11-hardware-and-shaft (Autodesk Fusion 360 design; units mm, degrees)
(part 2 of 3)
sketch "B Facet 180 Triangle 3" plane through (0, -75, 0) normal (0, -1, 0) x axis (-1, 0, 0)
  line L1 (60.9665, 27.066) -> (-2.067, -27.066)
  line L2 (124, -27.066) -> (60.9665, 27.066)
  line L3 (-2.067, -27.066) -> (124, -27.066)
  line L4 (60.9665, 21.7934) -> (8.7304, -23.066)
  line L5 (113.2026, -23.066) -> (60.9665, 21.7934)
  line L6 (8.7304, -23.066) -> (113.2026, -23.066)
  point P1 (0, 0)
  point P2 (-2.067, -27.066)
  point P3 (60.9665, 27.066)
  point P4 (124, -27.066)
  dimension "d477" distance P1 P2 = 2.067 (= "Linear Dimension-2")
  dimension "d478" distance P1 P2 = 27.066 (= "Linear Dimension-3")
  dimension "d479" distance P1 P3 = 60.9665 (= "Linear Dimension-4")
  dimension "d480" distance P1 P3 = 27.066 (= "Linear Dimension-5")
  dimension "d481" distance P1 P4 = 124 (= "Linear Dimension-6")
  dimension "d482" distance P1 P4 = 27.066 (= "Linear Dimension-7")
  dimension "d483" = 4 (= "memberWidth / 2")
extrude "Extrude14" cut sketch "B Facet 180 Triangle 3" profile of L5 L6 L4 against normal blind 4.7 (magnitude of "-( wall + 0.2 mm )")
sketch "B Facet 180 Triangle 4" plane through (0, -75, 0) normal (0, -1, 0) x axis (-1, 0, 0)
  line L1 (124, -27.066) -> (60.9665, 27.066)
  line L2 (124, 27.066) -> (124, -27.066)
  line L3 (60.9665, 27.066) -> (124, 27.066)
  line L4 (120, -18.3583) -> (71.7639, 23.066)
  line L5 (120, 23.066) -> (120, -18.3583)
  line L6 (71.7639, 23.066) -> (120, 23.066)
  point P1 (0, 0)
  point P2 (60.9665, 27.066)
  point P3 (124, -27.066)
  point P4 (124, 27.066)
  dimension "d486" distance P1 P2 = 60.9665 (= "Linear Dimension-2")
  dimension "d487" distance P1 P2 = 27.066 (= "Linear Dimension-3")
  dimension "d488" distance P1 P3 = 124 (= "Linear Dimension-4")
  dimension "d489" distance P1 P3 = 27.066 (= "Linear Dimension-5")
  dimension "d490" distance P1 P4 = 124 (= "Linear Dimension-6")
  dimension "d491" distance P1 P4 = 27.066 (= "Linear Dimension-7")
  dimension "d492" = -4 (= "-memberWidth / 2")
extrude "Extrude15" cut sketch "B Facet 180 Triangle 4" profile of L5 L6 L4 against normal blind 4.7 (magnitude of "-( wall + 0.2 mm )")
fillet "Fillet5" radius 1.5 (= "apertureRadius")
work_plane "WorkPlane11" RotateAngle 135 ExtraOffset 0
work_plane "WorkPlane12" AlongDistance 75 (= "bodyWidth / 2") ExtraOffset 0
sketch "B Facet 225 Triangle 1" plane through (0, -53.033, -53.033) normal (0, -0.7071, -0.7071) x axis (1, 0, 0)
  line L1 (23.9949, -27.066) -> (62.2721, 27.066)
  line L2 (0.1814, 27.066) -> (23.9949, -27.066)
  line L3 (62.2721, 27.066) -> (0.1814, 27.066)
  line L4 (24.81, -18.9852) -> (54.5447, 23.066)
  line L5 (6.311, 23.066) -> (24.81, -18.9852)
  line L6 (54.5447, 23.066) -> (6.311, 23.066)
  point P1 (0, 0)
  point P2 (62.2721, 27.066)
  point P3 (23.9949, -27.066)
  point P4 (0.1814, 27.066)
  dimension "d501" distance P1 P2 = 62.2721 (= "Linear Dimension-2")
  dimension "d502" distance P1 P2 = 27.066 (= "Linear Dimension-3")
  dimension "d503" distance P1 P3 = 23.9949 (= "Linear Dimension-4")
  dimension "d504" distance P1 P3 = 27.066 (= "Linear Dimension-5")
  dimension "d505" distance P1 P4 = 0.1814 (= "Linear Dimension-6")
  dimension "d506" distance P1 P4 = 27.066 (= "Linear Dimension-7")
  dimension "d507" = 4 (= "memberWidth / 2")
extrude "Extrude16" cut sketch "B Facet 225 Triangle 1" profile of L5 L6 L4 against normal blind 4.7 (magnitude of "-( wall + 0.2 mm )")
sketch "B Facet 225 Triangle 2" plane through (0, -53.033, -53.033) normal (0, -0.7071, -0.7071) x axis (1, 0, 0)
  line L1 (0.1814, 27.066) -> (23.9949, -27.066)
  line L2 (-74.6684, -27.066) -> (0.1814, 27.066)
  line L3 (23.9949, -27.066) -> (-74.6684, -27.066)
  line L4 (-1.4863, 20.9235) -> (17.8653, -23.066)
  line L5 (-62.3117, -23.066) -> (-1.4863, 20.9235)
  line L6 (17.8653, -23.066) -> (-62.3117, -23.066)
  point P1 (0, 0)
  point P2 (23.9949, -27.066)
  point P3 (0.1814, 27.066)
  point P4 (-74.6684, -27.066)
  dimension "d510" distance P1 P2 = 23.9949 (= "Linear Dimension-2")
  dimension "d511" distance P1 P2 = 27.066 (= "Linear Dimension-3")
  dimension "d512" distance P1 P3 = 0.1814 (= "Linear Dimension-4")
  dimension "d513" distance P1 P3 = 27.066 (= "Linear Dimension-5")
  dimension "d514" distance P1 P4 = 74.6684 (= "Linear Dimension-6")
  dimension "d515" distance P1 P4 = 27.066 (= "Linear Dimension-7")
  dimension "d516" = -4 (= "-memberWidth / 2")
extrude "Extrude17" cut sketch "B Facet 225 Triangle 2" profile of L5 L6 L4 against normal blind 4.7 (magnitude of "-( wall + 0.2 mm )")
sketch "B Facet 225 Triangle 3" plane through (0, -53.033, -53.033) normal (0, -0.7071, -0.7071) x axis (1, 0, 0)
  line L1 (-74.6684, -27.066) -> (0.1814, 27.066)
  line L2 (-124, 27.066) -> (-74.6684, -27.066)
  line L3 (0.1814, 27.066) -> (-124, 27.066)
  line L4 (-74.1179, -21.7315) -> (-12.1753, 23.066)
  line L5 (-114.9429, 23.066) -> (-74.1179, -21.7315)
  line L6 (-12.1753, 23.066) -> (-114.9429, 23.066)
  point P1 (0, 0)
  point P2 (0.1814, 27.066)
  point P3 (-74.6684, -27.066)
  point P4 (-124, 27.066)
  dimension "d519" distance P1 P2 = 0.1814 (= "Linear Dimension-2")
  dimension "d520" distance P1 P2 = 27.066 (= "Linear Dimension-3")
  dimension "d521" distance P1 P3 = 74.6684 (= "Linear Dimension-4")
  dimension "d522" distance P1 P3 = 27.066 (= "Linear Dimension-5")
  dimension "d523" distance P1 P4 = 124 (= "Linear Dimension-6")
  dimension "d524" distance P1 P4 = 27.066 (= "Linear Dimension-7")
  dimension "d525" = 4 (= "memberWidth / 2")
extrude "Extrude18" cut sketch "B Facet 225 Triangle 3" profile of L5 L6 L4 against normal blind 4.7 (magnitude of "-( wall + 0.2 mm )")
sketch "B Facet 225 Triangle 4" plane through (0, -53.033, -53.033) normal (0, -0.7071, -0.7071) x axis (1, 0, 0)
  line L1 (-124, 27.066) -> (-74.6684, -27.066)
  line L2 (-124, -27.066) -> (-124, 27.066)
  line L3 (-74.6684, -27.066) -> (-124, -27.066)
  line L4 (-120, 16.7383) -> (-83.7255, -23.066)
  line L5 (-120, -23.066) -> (-120, 16.7383)
  line L6 (-83.7255, -23.066) -> (-120, -23.066)
  point P1 (0, 0)
  point P2 (-74.6684, -27.066)
  point P3 (-124, 27.066)
  point P4 (-124, -27.066)
  dimension "d528" distance P1 P2 = 74.6684 (= "Linear Dimension-2")
  dimension "d529" distance P1 P2 = 27.066 (= "Linear Dimension-3")
  dimension "d530" distance P1 P3 = 124 (= "Linear Dimension-4")
  dimension "d531" distance P1 P3 = 27.066 (= "Linear Dimension-5")
  dimension "d532" distance P1 P4 = 124 (= "Linear Dimension-6")
  dimension "d533" distance P1 P4 = 27.066 (= "Linear Dimension-7")
  dimension "d534" = -4 (= "-memberWidth / 2")
extrude "Extrude19" cut sketch "B Facet 225 Triangle 4" profile of L5 L6 L4 against normal blind 4.7 (magnitude of "-( wall + 0.2 mm )")
fillet "Fillet6" radius 1.5 (= "apertureRadius")
work_plane "WorkPlane13" RotateAngle 180 ExtraOffset 0
work_plane "WorkPlane14" AlongDistance 75 (= "bodyWidth / 2") ExtraOffset 0
sketch "B Facet 270 Triangle 1" plane through (0, 0, -75) normal (0, 0, -1) x axis (-1, 0, 0)
  line L1 (36.9655, 27.066) -> (-17.1665, -27.066)
  line L2 (53.4167, -27.066) -> (36.9655, 27.066)
  line L3 (-17.1665, -27.066) -> (53.4167, -27.066)
  line L4 (35.0777, 19.5214) -> (-7.5097, -23.066)
  line L5 (48.0205, -23.066) -> (35.0777, 19.5214)
  line L6 (-7.5097, -23.066) -> (48.0205, -23.066)
  point P1 (0, 0)
  point P2 (-17.1665, -27.066)
  point P3 (36.9655, 27.066)
  point P4 (53.4167, -27.066)
  dimension "d543" distance P1 P2 = 17.1665 (= "Linear Dimension-2")
  dimension "d544" distance P1 P2 = 27.066 (= "Linear Dimension-3")
  dimension "d545" distance P1 P3 = 36.9655 (= "Linear Dimension-4")
  dimension "d546" distance P1 P3 = 27.066 (= "Linear Dimension-5")
  dimension "d547" distance P1 P4 = 53.4167 (= "Linear Dimension-6")
  dimension "d548" distance P1 P4 = 27.066 (= "Linear Dimension-7")
  dimension "d549" = 4 (= "memberWidth / 2")
extrude "Extrude20" cut sketch "B Facet 270 Triangle 1" profile of L5 L6 L4 against normal blind 4.7 (magnitude of "-( wall + 0.2 mm )")
sketch "B Facet 270 Triangle 2" plane through (0, 0, -75) normal (0, 0, -1) x axis (-1, 0, 0)
  line L1 (53.4167, -27.066) -> (36.9655, 27.066)
  line L2 (124, 27.066) -> (53.4167, -27.066)
  line L3 (36.9655, 27.066) -> (124, 27.066)
  line L4 (55.5648, -20.3777) -> (42.3618, 23.066)
  line L5 (112.2115, 23.066) -> (55.5648, -20.3777)
  line L6 (42.3618, 23.066) -> (112.2115, 23.066)
  point P1 (0, 0)
  point P2 (36.9655, 27.066)
  point P3 (53.4167, -27.066)
  point P4 (124, 27.066)
  dimension "d552" distance P1 P2 = 36.9655 (= "Linear Dimension-2")
  dimension "d553" distance P1 P2 = 27.066 (= "Linear Dimension-3")
  dimension "d554" distance P1 P3 = 53.4167 (= "Linear Dimension-4")
  dimension "d555" distance P1 P3 = 27.066 (= "Linear Dimension-5")
  dimension "d556" distance P1 P4 = 124 (= "Linear Dimension-6")
  dimension "d557" distance P1 P4 = 27.066 (= "Linear Dimension-7")
  dimension "d558" = -4 (= "-memberWidth / 2")
extrude "Extrude21" cut sketch "B Facet 270 Triangle 2" profile of L5 L6 L4 against normal blind 4.7 (magnitude of "-( wall + 0.2 mm )")
sketch "B Facet 270 Triangle 3" plane through (0, 0, -75) normal (0, 0, -1) x axis (-1, 0, 0)
  line L1 (124, 27.066) -> (53.4167, -27.066)
  line L2 (124, -27.066) -> (124, 27.066)
  line L3 (53.4167, -27.066) -> (124, -27.066)
  line L4 (120, 18.9574) -> (65.2053, -23.066)
  line L5 (120, -23.066) -> (120, 18.9574)
  line L6 (65.2053, -23.066) -> (120, -23.066)
  point P1 (0, 0)
  point P2 (53.4167, -27.066)
  point P3 (124, 27.066)
  point P4 (124, -27.066)
  dimension "d561" distance P1 P2 = 53.4167 (= "Linear Dimension-2")
  dimension "d562" distance P1 P2 = 27.066 (= "Linear Dimension-3")
  dimension "d563" distance P1 P3 = 124 (= "Linear Dimension-4")
  dimension "d564" distance P1 P3 = 27.066 (= "Linear Dimension-5")
  dimension "d565" distance P1 P4 = 124 (= "Linear Dimension-6")
  dimension "d566" distance P1 P4 = 27.066 (= "Linear Dimension-7")
  dimension "d567" = 4 (= "memberWidth / 2")
extrude "Extrude22" cut sketch "B Facet 270 Triangle 3" profile of L5 L6 L4 against normal blind 4.7 (magnitude of "-( wall + 0.2 mm )")
fillet "Fillet7" radius 1.5 (= "apertureRadius")
work_plane "WorkPlane15" RotateAngle 225 ExtraOffset 0
work_plane "WorkPlane16" AlongDistance 75 (= "bodyWidth / 2") ExtraOffset 0
sketch "B Facet 315 Triangle 1" plane through (0, 53.033, -53.033) normal (0, 0.7071, -0.7071) x axis (1, 0, 0)
  line L1 (-82.0711, -27.066) -> (-43.7939, 27.066)
  line L2 (-124, 27.066) -> (-82.0711, -27.066)
  line L3 (-43.7939, 27.066) -> (-124, 27.066)
  line L4 (-82.2175, -20.3449) -> (-51.5213, 23.066)
  line L5 (-115.8422, 23.066) -> (-82.2175, -20.3449)
  line L6 (-51.5213, 23.066) -> (-115.8422, 23.066)
  point P1 (0, 0)
  point P2 (-43.7939, 27.066)
  point P3 (-82.0711, -27.066)
  point P4 (-124, 27.066)
  dimension "d576" distance P1 P2 = 43.7939 (= "Linear Dimension-2")
  dimension "d577" distance P1 P2 = 27.066 (= "Linear Dimension-3")
  dimension "d578" distance P1 P3 = 82.0711 (= "Linear Dimension-4")
  dimension "d579" distance P1 P3 = 27.066 (= "Linear Dimension-5")
  dimension "d580" distance P1 P4 = 124 (= "Linear Dimension-6")
  dimension "d581" distance P1 P4 = 27.066 (= "Linear Dimension-7")
  dimension "d582" = 4 (= "memberWidth / 2")
extrude "Extrude23" cut sketch "B Facet 315 Triangle 1" profile of L5 L6 L4 against normal blind 4.7 (magnitude of "-( wall + 0.2 mm )")
sketch "B Facet 315 Triangle 2" plane through (0, 53.033, -53.033) normal (0, 0.7071, -0.7071) x axis (1, 0, 0)
  line L1 (-124, 27.066) -> (-82.0711, -27.066)
  line L2 (-124, -27.066) -> (-124, 27.066)
  line L3 (-82.0711, -27.066) -> (-124, -27.066)
  line L4 (-120, 15.3697) -> (-90.2289, -23.066)
  line L5 (-120, -23.066) -> (-120, 15.3697)
  line L6 (-90.2289, -23.066) -> (-120, -23.066)
  point P1 (0, 0)
  point P2 (-82.0711, -27.066)
  point P3 (-124, 27.066)
  point P4 (-124, -27.066)
  dimension "d585" distance P1 P2 = 82.0711 (= "Linear Dimension-2")
  dimension "d586" distance P1 P2 = 27.066 (= "Linear Dimension-3")
  dimension "d587" distance P1 P3 = 124 (= "Linear Dimension-4")
  dimension "d588" distance P1 P3 = 27.066 (= "Linear Dimension-5")
  dimension "d589" distance P1 P4 = 124 (= "Linear Dimension-6")
  dimension "d590" distance P1 P4 = 27.066 (= "Linear Dimension-7")
  dimension "d591" = -4 (= "-memberWidth / 2")
extrude "Extrude24" cut sketch "B Facet 315 Triangle 2" profile of L5 L6 L4 against normal blind 4.7 (magnitude of "-( wall + 0.2 mm )")
fillet "Fillet8" radius 1.5 (= "apertureRadius")
work_plane "WorkPlane17" AlongDistance 0.5 (= "qFront") ExtraOffset 0
sketch "A Central Carrier sketch" plane through (0.3536, 0.3536, 0) normal (0.7071, 0.7071, 0) x axis (0, 0, 1)
  circle C1 centre (0, 0) radius 26
  dimension "d598" diameter C1 = 52 (= "carrierOD")
extrude "Extrude25" new body sketch "A Central Carrier sketch" along normal blind 18 (= "spokeDepth")
work_plane "WorkPlane18" AlongDistance 0.5 (= "qFront") ExtraOffset 0
sketch "A Spoke 1 Profile" plane through (0.3536, 0.3536, 0) normal (0.7071, 0.7071, 0) x axis (0, 0, 1)
  line L1 (37.3643, -145.3579) -> (-4.7984, -1.4054)
  line L2 (46.9611, -142.547) -> (37.3643, -145.3579)
  line L3 (4.7984, 1.4054) -> (46.9611, -142.547)
  line L4 (-4.7984, -1.4054) -> (4.7984, 1.4054)
  point P1 (0, 0)
  point P2 (-4.7984, -1.4054)
  point P3 (37.3643, -145.3579)
  point P4 (46.9611, -142.547)
  point P5 (4.7984, 1.4054)
  dimension "d603" distance P1 P2 = 4.7984 (= "Linear Dimension-2")
  dimension "d604" distance P1 P2 = 1.4054 (= "Linear Dimension-3")
  dimension "d605" distance P1 P3 = 37.3643 (= "Linear Dimension-4")
  dimension "d606" distance P1 P3 = 145.3579 (= "Linear Dimension-5")
  dimension "d607" distance P1 P4 = 46.9611 (= "Linear Dimension-6")
  dimension "d608" distance P1 P4 = 142.547 (= "Linear Dimension-7")
  dimension "d609" distance P1 P5 = 4.7984 (= "Linear Dimension-8")
  dimension "d610" distance P1 P5 = 1.4054 (= "Linear Dimension-9")
extrude "Extrude26" add sketch "A Spoke 1 Profile" along normal blind 18 (= "spokeDepth")
sketch "A Spoke 2 Profile" plane through (0.3536, 0.3536, 0) normal (0.7071, 0.7071, 0) x axis (0, 0, 1)
  line L1 (126.9012, -80.1317) -> (-2.5272, -4.3143)
  line L2 (131.9557, -71.5031) -> (126.9012, -80.1317)
  line L3 (2.5272, 4.3143) -> (131.9557, -71.5031)
  line L4 (-2.5272, -4.3143) -> (2.5272, 4.3143)
  point P1 (0, 0)
  point P2 (-2.5272, -4.3143)
  point P3 (126.9012, -80.1317)
  point P4 (131.9557, -71.5031)
  point P5 (2.5272, 4.3143)
  dimension "d613" distance P1 P2 = 2.5272 (= "Linear Dimension-2")
  dimension "d614" distance P1 P2 = 4.3143 (= "Linear Dimension-3")
  dimension "d615" distance P1 P3 = 126.9012 (= "Linear Dimension-4")
  dimension "d616" distance P1 P3 = 80.1317 (= "Linear Dimension-5")
  dimension "d617" distance P1 P4 = 131.9557 (= "Linear Dimension-6")
  dimension "d618" distance P1 P4 = 71.5031 (= "Linear Dimension-7")
  dimension "d619" distance P1 P5 = 2.5272 (= "Linear Dimension-8")
  dimension "d620" distance P1 P5 = 4.3143 (= "Linear Dimension-9")
extrude "Extrude27" add sketch "A Spoke 2 Profile" along normal blind 18 (= "spokeDepth")
sketch "A Spoke 3 Profile" plane through (0.3536, 0.3536, 0) normal (0.7071, 0.7071, 0) x axis (0, 0, 1)
  line L1 (131.9557, 71.5031) -> (2.5272, -4.3143)
  line L2 (126.9012, 80.1317) -> (131.9557, 71.5031)
  line L3 (-2.5272, 4.3143) -> (126.9012, 80.1317)
  line L4 (2.5272, -4.3143) -> (-2.5272, 4.3143)
  point P1 (0, 0)
  point P2 (2.5272, -4.3143)
  point P3 (131.9557, 71.5031)
  point P4 (126.9012, 80.1317)
  point P5 (-2.5272, 4.3143)
  dimension "d623" distance P1 P2 = 2.5272 (= "Linear Dimension-2")
  dimension "d624" distance P1 P2 = 4.3143 (= "Linear Dimension-3")
  dimension "d625" distance P1 P3 = 131.9557 (= "Linear Dimension-4")
  dimension "d626" distance P1 P3 = 71.5031 (= "Linear Dimension-5")
  dimension "d627" distance P1 P4 = 126.9012 (= "Linear Dimension-6")
  dimension "d628" distance P1 P4 = 80.1317 (= "Linear Dimension-7")
  dimension "d629" distance P1 P5 = 2.5272 (= "Linear Dimension-8")
  dimension "d630" distance P1 P5 = 4.3143 (= "Linear Dimension-9")
extrude "Extrude28" add sketch "A Spoke 3 Profile" along normal blind 18 (= "spokeDepth")
sketch "A Spoke 4 Profile" plane through (0.3536, 0.3536, 0) normal (0.7071, 0.7071, 0) x axis (0, 0, 1)
  line L1 (46.9611, 142.547) -> (4.7984, -1.4054)
  line L2 (37.3643, 145.3579) -> (46.9611, 142.547)
  line L3 (-4.7984, 1.4054) -> (37.3643, 145.3579)
  line L4 (4.7984, -1.4054) -> (-4.7984, 1.4054)
  point P1 (0, 0)
  point P2 (4.7984, -1.4054)
  point P3 (46.9611, 142.547)
  point P4 (37.3643, 145.3579)
  point P5 (-4.7984, 1.4054)
  dimension "d633" distance P1 P2 = 4.7984 (= "Linear Dimension-2")
  dimension "d634" distance P1 P2 = 1.4054 (= "Linear Dimension-3")
  dimension "d635" distance P1 P3 = 46.9611 (= "Linear Dimension-4")
  dimension "d636" distance P1 P3 = 142.547 (= "Linear Dimension-5")
  dimension "d637" distance P1 P4 = 37.3643 (= "Linear Dimension-6")
  dimension "d638" distance P1 P4 = 145.3579 (= "Linear Dimension-7")
  dimension "d639" distance P1 P5 = 4.7984 (= "Linear Dimension-8")
  dimension "d640" distance P1 P5 = 1.4054 (= "Linear Dimension-9")
extrude "Extrude29" add sketch "A Spoke 4 Profile" along normal blind 18 (= "spokeDepth")
sketch "A Spoke 5 Profile" plane through (0.3536, 0.3536, 0) normal (0.7071, 0.7071, 0) x axis (0, 0, 1)
  line L1 (-37.3643, 145.3579) -> (4.7984, 1.4054)
  line L2 (-46.9611, 142.547) -> (-37.3643, 145.3579)
  line L3 (-4.7984, -1.4054) -> (-46.9611, 142.547)
  line L4 (4.7984, 1.4054) -> (-4.7984, -1.4054)
  point P1 (0, 0)
  point P2 (4.7984, 1.4054)
  point P3 (-37.3643, 145.3579)
  point P4 (-46.9611, 142.547)
  point P5 (-4.7984, -1.4054)
  dimension "d643" distance P1 P2 = 4.7984 (= "Linear Dimension-2")
  dimension "d644" distance P1 P2 = 1.4054 (= "Linear Dimension-3")
  dimension "d645" distance P1 P3 = 37.3643 (= "Linear Dimension-4")
  dimension "d646" distance P1 P3 = 145.3579 (= "Linear Dimension-5")
  dimension "d647" distance P1 P4 = 46.9611 (= "Linear Dimension-6")
  dimension "d648" distance P1 P4 = 142.547 (= "Linear Dimension-7")
  dimension "d649" distance P1 P5 = 4.7984 (= "Linear Dimension-8")
  dimension "d650" distance P1 P5 = 1.4054 (= "Linear Dimension-9")
extrude "Extrude30" add sketch "A Spoke 5 Profile" along normal blind 18 (= "spokeDepth")
sketch "A Spoke 6 Profile" plane through (0.3536, 0.3536, 0) normal (0.7071, 0.7071, 0) x axis (0, 0, 1)
  line L1 (-126.9012, 80.1317) -> (2.5272, 4.3143)
  line L2 (-131.9557, 71.5031) -> (-126.9012, 80.1317)
  line L3 (-2.5272, -4.3143) -> (-131.9557, 71.5031)
  line L4 (2.5272, 4.3143) -> (-2.5272, -4.3143)
  point P1 (0, 0)
  point P2 (2.5272, 4.3143)
  point P3 (-126.9012, 80.1317)
  point P4 (-131.9557, 71.5031)
  point P5 (-2.5272, -4.3143)
  dimension "d653" distance P1 P2 = 2.5272 (= "Linear Dimension-2")
  dimension "d654" distance P1 P2 = 4.3143 (= "Linear Dimension-3")
  dimension "d655" distance P1 P3 = 126.9012 (= "Linear Dimension-4")
  dimension "d656" distance P1 P3 = 80.1317 (= "Linear Dimension-5")
  dimension "d657" distance P1 P4 = 131.9557 (= "Linear Dimension-6")
  dimension "d658" distance P1 P4 = 71.5031 (= "Linear Dimension-7")
  dimension "d659" distance P1 P5 = 2.5272 (= "Linear Dimension-8")
  dimension "d660" distance P1 P5 = 4.3143 (= "Linear Dimension-9")
extrude "Extrude31" add sketch "A Spoke 6 Profile" along normal blind 18 (= "spokeDepth")
sketch "A Spoke 7 Profile" plane through (0.3536, 0.3536, 0) normal (0.7071, 0.7071, 0) x axis (0, 0, 1)
  line L1 (-131.9557, -71.5031) -> (-2.5272, 4.3143)
  line L2 (-126.9012, -80.1317) -> (-131.9557, -71.5031)
  line L3 (2.5272, -4.3143) -> (-126.9012, -80.1317)
  line L4 (-2.5272, 4.3143) -> (2.5272, -4.3143)
  point P1 (0, 0)
  point P2 (-2.5272, 4.3143)
  point P3 (-131.9557, -71.5031)
  point P4 (-126.9012, -80.1317)
  point P5 (2.5272, -4.3143)
  dimension "d663" distance P1 P2 = 2.5272 (= "Linear Dimension-2")
  dimension "d664" distance P1 P2 = 4.3143 (= "Linear Dimension-3")
  dimension "d665" distance P1 P3 = 131.9557 (= "Linear Dimension-4")
  dimension "d666" distance P1 P3 = 71.5031 (= "Linear Dimension-5")
  dimension "d667" distance P1 P4 = 126.9012 (= "Linear Dimension-6")
  dimension "d668" distance P1 P4 = 80.1317 (= "Linear Dimension-7")
  dimension "d669" distance P1 P5 = 2.5272 (= "Linear Dimension-8")
  dimension "d670" distance P1 P5 = 4.3143 (= "Linear Dimension-9")
extrude "Extrude32" add sketch "A Spoke 7 Profile" along normal blind 18 (= "spokeDepth")
sketch "A Spoke 8 Profile" plane through (0.3536, 0.3536, 0) normal (0.7071, 0.7071, 0) x axis (0, 0, 1)
  line L1 (-46.9611, -142.547) -> (-4.7984, 1.4054)
  line L2 (-37.3643, -145.3579) -> (-46.9611, -142.547)
  line L3 (4.7984, 1.4054) -> (-37.3643, -145.3579)
  line L4 (-4.7984, 1.4054) -> (4.7984, 1.4054)
  point P1 (0, 0)
  point P2 (-4.7984, 1.4054)
  point P3 (-46.9611, -142.547)
  point P4 (-37.3643, -145.3579)
  point P5 (4.7984, 1.4054)
  dimension "d673" distance P1 P2 = 4.7984 (= "Linear Dimension-2")
  dimension "d674" distance P1 P2 = 1.4054 (= "Linear Dimension-3")
  dimension "d675" distance P1 P3 = 46.9611 (= "Linear Dimension-4")
  dimension "d676" distance P1 P3 = 142.547 (= "Linear Dimension-5")
  dimension "d677" distance P1 P4 = 37.3643 (= "Linear Dimension-6")
  dimension "d678" distance P1 P4 = 145.3579 (= "Linear Dimension-7")
  dimension "d679" distance P1 P5 = 4.7984 (= "Linear Dimension-8")
  dimension "d680" distance P1 P5 = 1.4054 (= "Linear Dimension-9")
extrude "Extrude33" add sketch "A Spoke 8 Profile" along normal blind 18 (= "spokeDepth")
sketch "Spoke Outer Envelope" plane through (0, 0, 0) normal (1, 0, 0) x axis (0, 0, -1)
  line L1 (31.066, 75) -> (75, 31.066)
  line L2 (-31.066, 75) -> (31.066, 75)
  line L3 (-75, 31.066) -> (-31.066, 75)
  line L4 (-75, -31.066) -> (-75, 31.066)
  line L5 (-31.066, -75) -> (-75, -31.066)
  line L6 (31.066, -75) -> (-31.066, -75)
  line L7 (75, -31.066) -> (31.066, -75)
  line L8 (75, 31.066) -> (75, -31.066)
  point P1 (0, 0)
  point P10 (0, 0)
  point P3 (31.066, 75)
  point P8 (31.066, -75)
  coincident P1 P10
  horizontal L2
  dimension "d683" distance P3 P8 = 150 (= "bodyWidth")
extrude "Extrude34" sketch "Spoke Outer Envelope" distance 260 (= "bodyLength")
fillet "Fillet9" radius 1 (= "rootRadius")
work_plane "WorkPlane19" AlongDistance 10.6 (= "qFrontBack") ExtraOffset 0
sketch "A Rear Carrier Clearance sketch" plane through (7.4953, 7.4953, 0) normal (0.7071, 0.7071, 0) x axis (0, 0, 1)
  circle C1 centre (0, 0) radius 23
  dimension "d690" diameter C1 = 46 (= "rearCarrierClearance")
extrude "Extrude35" cut sketch "A Rear Carrier Clearance sketch" along normal blind 18 (= "spokeDepth")
work_plane "WorkPlane20" AlongDistance 0.5 (= "qFront") ExtraOffset 0
sketch "A Seal Relief sketch" plane through (0.3536, 0.3536, 0) normal (0.7071, 0.7071, 0) x axis (0, 0, 1)
  circle C1 centre (0, 0) radius 9.75
  dimension "d695" diameter C1 = 19.5 (= "raceRelief")
extrude "Extrude36" cut sketch "A Seal Relief sketch" along normal blind 10.1 (= "frontSeatDepth + shoulder")
work_plane "WorkPlane21" AlongDistance 0.5 (= "qFront") ExtraOffset 0
sketch "A Front Bearing Seat sketch" plane through (0.3536, 0.3536, 0) normal (0.7071, 0.7071, 0) x axis (0, 0, 1)
  circle C1 centre (0, 0) radius 11.1
  dimension "d700" diameter C1 = 22.2 (= "seatDiameter")
extrude "Extrude37" cut sketch "A Front Bearing Seat sketch" along normal blind 7.1 (= "frontSeatDepth")
work_plane "WorkPlane22" AlongDistance 0.5 (= "qFront") ExtraOffset 0
sketch "A Support Bolt seed" plane through (0.3536, 0.3536, 0) normal (0.7071, 0.7071, 0) x axis (0, 0, 1)
  line L1 (17, 0) -> (0, 0)
  circle C1 centre (17, 0) radius 1.65
  point P1 (0, 0)
  point P2 (17, 0)
  horizontal L1
  dimension "d705" distance P1 P2 = 17 (= "supportCircle / 2")
  dimension "d706" diameter C1 = 3.3 (= "m3Clearance")
extrude "Extrude38" cut sketch "A Support Bolt seed" profile of C1 along normal blind 10.1 (= "frontSeatDepth + shoulder")
circular_pattern "C-Pattern1" TotalAngle 360
work_plane "WorkPlane23" AlongDistance 0.5 (= "qFront") ExtraOffset 0
sketch "A Front Bearing Boss sketch" plane through (0.3536, 0.3536, 0) normal (0.7071, 0.7071, 0) x axis (0, 0, 1)
  circle C1 centre (0, 0) radius 22
  dimension "d713" diameter C1 = 44 (= "coreOD")
chamfer "Chamfer1" distance 0.4 (= "entryChamfer")
work_plane "WorkPlane24" AlongDistance 75 (= "bodyWidth / 2") ExtraOffset 0
sketch "A Collar Driver Corridors" plane through (0, 0, 75) normal (0, 0, 1) x axis (1, 0, 0)
  circle C1 centre (6.7175, 15.9099) radius 3
  circle C2 centre (15.9099, 6.7175) radius 3
  point P1 (0, 0)
  point P2 (6.7175, 15.9099)
  point P3 (15.9099, 6.7175)
  dimension "d717" distance P1 P2 = 6.7175 (= "abs(( 16 mm + ( -6.5 mm ) ) / sqrt(2))")
  dimension "d718" distance P1 P2 = 15.9099 (= "abs(( 16 mm - ( -6.5 mm ) ) / sqrt(2))")
  dimension "d719" diameter C1 = 6
  dimension "d720" distance P1 P3 = 15.9099 (= "abs(( 16 mm + ( 6.5 mm ) ) / sqrt(2))")
  dimension "d721" distance P1 P3 = 6.7175 (= "abs(( 16 mm - ( 6.5 mm ) ) / sqrt(2))")
  dimension "d722" diameter C2 = 6
extrude "Extrude39" cut sketch "A Collar Driver Corridors" against normal blind 75 (magnitude of "-( bodyWidth / 2 )")
work_plane "WorkPlane17" ExtraOffset 0
sketch "B Central Carrier sketch" plane through (-0.3536, -0.3536, 0) normal (0.7071, 0.7071, 0) x axis (0, 0, 1)
  circle C1 centre (0, 0) radius 38
  dimension "d727" diameter C1 = 76 (= "mountOD")
extrude "Extrude25" new body sketch "B Central Carrier sketch" no distance stored
work_plane "WorkPlane18" ExtraOffset 0
sketch "B Spoke 1 Profile" plane through (-0.3536, -0.3536, 0) normal (0.7071, 0.7071, 0) x axis (0, 0, 1)
  line L1 (37.3643, -145.3579) -> (-4.7984, -1.4054)
  line L2 (46.9611, -142.547) -> (37.3643, -145.3579)
  line L3 (4.7984, 1.4054) -> (46.9611, -142.547)
  line L4 (-4.7984, -1.4054) -> (4.7984, 1.4054)
  point P1 (0, 0)
  point P2 (-4.7984, -1.4054)
  point P3 (37.3643, -145.3579)
  point P4 (46.9611, -142.547)
  point P5 (4.7984, 1.4054)
  dimension "d732" distance P1 P2 = 4.7984 (= "Linear Dimension-2")
  dimension "d733" distance P1 P2 = 1.4054 (= "Linear Dimension-3")
  dimension "d734" distance P1 P3 = 37.3643 (= "Linear Dimension-4")
  dimension "d735" distance P1 P3 = 145.3579 (= "Linear Dimension-5")
  dimension "d736" distance P1 P4 = 46.9611 (= "Linear Dimension-6")
  dimension "d737" distance P1 P4 = 142.547 (= "Linear Dimension-7")
  dimension "d738" distance P1 P5 = 4.7984 (= "Linear Dimension-8")
  dimension "d739" distance P1 P5 = 1.4054 (= "Linear Dimension-9")
extrude "Extrude26" add sketch "B Spoke 1 Profile" no distance stored
sketch "B Spoke 2 Profile" plane through (-0.3536, -0.3536, 0) normal (0.7071, 0.7071, 0) x axis (0, 0, 1)
  line L1 (126.9012, -80.1317) -> (-2.5272, -4.3143)
  line L2 (131.9557, -71.5031) -> (126.9012, -80.1317)
  line L3 (2.5272, 4.3143) -> (131.9557, -71.5031)
  line L4 (-2.5272, -4.3143) -> (2.5272, 4.3143)
  point P1 (0, 0)
  point P2 (-2.5272, -4.3143)
  point P3 (126.9012, -80.1317)
  point P4 (131.9557, -71.5031)
  point P5 (2.5272, 4.3143)
  dimension "d742" distance P1 P2 = 2.5272 (= "Linear Dimension-2")
  dimension "d743" distance P1 P2 = 4.3143 (= "Linear Dimension-3")
  dimension "d744" distance P1 P3 = 126.9012 (= "Linear Dimension-4")
  dimension "d745" distance P1 P3 = 80.1317 (= "Linear Dimension-5")
  dimension "d746" distance P1 P4 = 131.9557 (= "Linear Dimension-6")
  dimension "d747" distance P1 P4 = 71.5031 (= "Linear Dimension-7")
  dimension "d748" distance P1 P5 = 2.5272 (= "Linear Dimension-8")
  dimension "d749" distance P1 P5 = 4.3143 (= "Linear Dimension-9")
extrude "Extrude27" add sketch "B Spoke 2 Profile" no distance stored
sketch "B Spoke 3 Profile" plane through (-0.3536, -0.3536, 0) normal (0.7071, 0.7071, 0) x axis (0, 0, 1)
  line L1 (131.9557, 71.5031) -> (2.5272, -4.3143)
  line L2 (126.9012, 80.1317) -> (131.9557, 71.5031)
  line L3 (-2.5272, 4.3143) -> (126.9012, 80.1317)
  line L4 (2.5272, -4.3143) -> (-2.5272, 4.3143)
  point P1 (0, 0)
  point P2 (2.5272, -4.3143)
  point P3 (131.9557, 71.5031)
  point P4 (126.9012, 80.1317)
  point P5 (-2.5272, 4.3143)
  dimension "d752" distance P1 P2 = 2.5272 (= "Linear Dimension-2")
  dimension "d753" distance P1 P2 = 4.3143 (= "Linear Dimension-3")
  dimension "d754" distance P1 P3 = 131.9557 (= "Linear Dimension-4")
  dimension "d755" distance P1 P3 = 71.5031 (= "Linear Dimension-5")
  dimension "d756" distance P1 P4 = 126.9012 (= "Linear Dimension-6")
  dimension "d757" distance P1 P4 = 80.1317 (= "Linear Dimension-7")
  dimension "d758" distance P1 P5 = 2.5272 (= "Linear Dimension-8")
  dimension "d759" distance P1 P5 = 4.3143 (= "Linear Dimension-9")
extrude "Extrude28" add sketch "B Spoke 3 Profile" no distance stored
sketch "B Spoke 4 Profile" plane through (-0.3536, -0.3536, 0) normal (0.7071, 0.7071, 0) x axis (0, 0, 1)
  line L1 (46.9611, 142.547) -> (4.7984, -1.4054)
  line L2 (37.3643, 145.3579) -> (46.9611, 142.547)
  line L3 (-4.7984, 1.4054) -> (37.3643, 145.3579)
  line L4 (4.7984, -1.4054) -> (-4.7984, 1.4054)
  point P1 (0, 0)
  point P2 (4.7984, -1.4054)
  point P3 (46.9611, 142.547)
  point P4 (37.3643, 145.3579)
  point P5 (-4.7984, 1.4054)
  dimension "d762" distance P1 P2 = 4.7984 (= "Linear Dimension-2")
  dimension "d763" distance P1 P2 = 1.4054 (= "Linear Dimension-3")
  dimension "d764" distance P1 P3 = 46.9611 (= "Linear Dimension-4")
  dimension "d765" distance P1 P3 = 142.547 (= "Linear Dimension-5")
  dimension "d766" distance P1 P4 = 37.3643 (= "Linear Dimension-6")
  dimension "d767" distance P1 P4 = 145.3579 (= "Linear Dimension-7")
  dimension "d768" distance P1 P5 = 4.7984 (= "Linear Dimension-8")
  dimension "d769" distance P1 P5 = 1.4054 (= "Linear Dimension-9")
extrude "Extrude29" add sketch "B Spoke 4 Profile" no distance stored
sketch "B Spoke 5 Profile" plane through (-0.3536, -0.3536, 0) normal (0.7071, 0.7071, 0) x axis (0, 0, 1)
  line L1 (-37.3643, 145.3579) -> (4.7984, 1.4054)
  line L2 (-46.9611, 142.547) -> (-37.3643, 145.3579)
  line L3 (-4.7984, -1.4054) -> (-46.9611, 142.547)
  line L4 (4.7984, 1.4054) -> (-4.7984, -1.4054)
  point P1 (0, 0)
  point P2 (4.7984, 1.4054)
  point P3 (-37.3643, 145.3579)
  point P4 (-46.9611, 142.547)
  point P5 (-4.7984, -1.4054)
  dimension "d772" distance P1 P2 = 4.7984 (= "Linear Dimension-2")
  dimension "d773" distance P1 P2 = 1.4054 (= "Linear Dimension-3")
  dimension "d774" distance P1 P3 = 37.3643 (= "Linear Dimension-4")
  dimension "d775" distance P1 P3 = 145.3579 (= "Linear Dimension-5")
  dimension "d776" distance P1 P4 = 46.9611 (= "Linear Dimension-6")
  dimension "d777" distance P1 P4 = 142.547 (= "Linear Dimension-7")
  dimension "d778" distance P1 P5 = 4.7984 (= "Linear Dimension-8")
  dimension "d779" distance P1 P5 = 1.4054 (= "Linear Dimension-9")
extrude "Extrude30" add sketch "B Spoke 5 Profile" no distance stored
sketch "B Spoke 6 Profile" plane through (-0.3536, -0.3536, 0) normal (0.7071, 0.7071, 0) x axis (0, 0, 1)
  line L1 (-126.9012, 80.1317) -> (2.5272, 4.3143)
  line L2 (-131.9557, 71.5031) -> (-126.9012, 80.1317)
  line L3 (-2.5272, -4.3143) -> (-131.9557, 71.5031)
  line L4 (2.5272, 4.3143) -> (-2.5272, -4.3143)
  point P1 (0, 0)
  point P2 (2.5272, 4.3143)
  point P3 (-126.9012, 80.1317)
  point P4 (-131.9557, 71.5031)
  point P5 (-2.5272, -4.3143)
  dimension "d782" distance P1 P2 = 2.5272 (= "Linear Dimension-2")
  dimension "d783" distance P1 P2 = 4.3143 (= "Linear Dimension-3")
  dimension "d784" distance P1 P3 = 126.9012 (= "Linear Dimension-4")
  dimension "d785" distance P1 P3 = 80.1317 (= "Linear Dimension-5")
  dimension "d786" distance P1 P4 = 131.9557 (= "Linear Dimension-6")
  dimension "d787" distance P1 P4 = 71.5031 (= "Linear Dimension-7")
  dimension "d788" distance P1 P5 = 2.5272 (= "Linear Dimension-8")
  dimension "d789" distance P1 P5 = 4.3143 (= "Linear Dimension-9")
extrude "Extrude31" add sketch "B Spoke 6 Profile" no distance stored
sketch "B Spoke 7 Profile" plane through (-0.3536, -0.3536, 0) normal (0.7071, 0.7071, 0) x axis (0, 0, 1)
  line L1 (-131.9557, -71.5031) -> (-2.5272, 4.3143)
  line L2 (-126.9012, -80.1317) -> (-131.9557, -71.5031)
  line L3 (2.5272, -4.3143) -> (-126.9012, -80.1317)
  line L4 (-2.5272, 4.3143) -> (2.5272, -4.3143)
  point P1 (0, 0)
  point P2 (-2.5272, 4.3143)
  point P3 (-131.9557, -71.5031)
  point P4 (-126.9012, -80.1317)
  point P5 (2.5272, -4.3143)
  dimension "d792" distance P1 P2 = 2.5272 (= "Linear Dimension-2")
  dimension "d793" distance P1 P2 = 4.3143 (= "Linear Dimension-3")
  dimension "d794" distance P1 P3 = 131.9557 (= "Linear Dimension-4")
  dimension "d795" distance P1 P3 = 71.5031 (= "Linear Dimension-5")
  dimension "d796" distance P1 P4 = 126.9012 (= "Linear Dimension-6")
  dimension "d797" distance P1 P4 = 80.1317 (= "Linear Dimension-7")
  dimension "d798" distance P1 P5 = 2.5272 (= "Linear Dimension-8")
  dimension "d799" distance P1 P5 = 4.3143 (= "Linear Dimension-9")
extrude "Extrude32" add sketch "B Spoke 7 Profile" no distance stored
sketch "B Spoke 8 Profile" plane through (-0.3536, -0.3536, 0) normal (0.7071, 0.7071, 0) x axis (0, 0, 1)
  line L1 (-46.9611, -142.547) -> (-4.7984, 1.4054)
  line L2 (-37.3643, -145.3579) -> (-46.9611, -142.547)
  line L3 (4.7984, 1.4054) -> (-37.3643, -145.3579)
  line L4 (-4.7984, 1.4054) -> (4.7984, 1.4054)
  point P1 (0, 0)
  point P2 (-4.7984, 1.4054)
  point P3 (-46.9611, -142.547)
  point P4 (-37.3643, -145.3579)
  point P5 (4.7984, 1.4054)
  dimension "d802" distance P1 P2 = 4.7984 (= "Linear Dimension-2")
  dimension "d803" distance P1 P2 = 1.4054 (= "Linear Dimension-3")
  dimension "d804" distance P1 P3 = 46.9611 (= "Linear Dimension-4")
  dimension "d805" distance P1 P3 = 142.547 (= "Linear Dimension-5")
  dimension "d806" distance P1 P4 = 37.3643 (= "Linear Dimension-6")
  dimension "d807" distance P1 P4 = 145.3579 (= "Linear Dimension-7")
  dimension "d808" distance P1 P5 = 4.7984 (= "Linear Dimension-8")
  dimension "d809" distance P1 P5 = 1.4054 (= "Linear Dimension-9")
extrude "Extrude33" add sketch "B Spoke 8 Profile" no distance stored
sketch "Spoke Outer Envelope" plane through (0, 0, 0) normal (1, 0, 0) x axis (0, 0, -1)
  line L1 (31.066, 75) -> (75, 31.066)
  line L2 (-31.066, 75) -> (31.066, 75)
  line L3 (-75, 31.066) -> (-31.066, 75)
  line L4 (-75, -31.066) -> (-75, 31.066)
  line L5 (-31.066, -75) -> (-75, -31.066)
  line L6 (31.066, -75) -> (-31.066, -75)
  line L7 (75, -31.066) -> (31.066, -75)
  line L8 (75, 31.066) -> (75, -31.066)
  point P1 (0, 0)
  point P10 (0, 0)
  point P3 (31.066, 75)
  point P8 (31.066, -75)
  coincident P1 P10
  horizontal L2
  dimension "d812" distance P3 P8 = 150 (= "bodyWidth")
extrude "Extrude34" sketch "Spoke Outer Envelope" distance 260 (= "bodyLength")
fillet "Fillet9" radius 1 (= "rootRadius")
work_plane "WorkPlane19" ExtraOffset 0
sketch "B Open Hub Cavity sketch" plane through (-0.3536, -0.3536, 0) normal (0.7071, 0.7071, 0) x axis (0, 0, 1)
  circle C1 centre (0, 0) radius 25.15
  dimension "d819" diameter C1 = 50.3 (= "mountOpening")
extrude "Extrude35" cut sketch "B Open Hub Cavity sketch" no distance stored
work_plane "WorkPlane20" ExtraOffset 0
sketch "B Four Mount Holes" plane through (-0.3536, -0.3536, 0) normal (0.7071, 0.7071, 0) x axis (0, 0, 1)
  circle C1 centre (22.6274, 22.6274) radius 2.15
  circle C2 centre (-22.6274, 22.6274) radius 2.15
  circle C3 centre (-22.6274, -22.6274) radius 2.15
  circle C4 centre (22.6274, -22.6274) radius 2.15
  point P1 (0, 0)
  point P2 (22.6274, 22.6274)
  point P3 (-22.6274, 22.6274)
  point P4 (-22.6274, -22.6274)
  point P5 (22.6274, -22.6274)
  dimension "d824" distance P1 P2 = 22.6274 (= "abs(mountCircle / ( 2 * sqrt(2) ))")
  dimension "d825" distance P1 P2 = 22.6274 (= "abs(mountCircle / ( 2 * sqrt(2) ))")
  dimension "d826" diameter C1 = 4.3 (= "m4Clearance")
  dimension "d827" distance P1 P3 = 22.6274 (= "abs(-mountCircle / ( 2 * sqrt(2) ))")
  dimension "d828" distance P1 P3 = 22.6274 (= "abs(mountCircle / ( 2 * sqrt(2) ))")
  dimension "d829" diameter C2 = 4.3 (= "m4Clearance")
  dimension "d830" distance P1 P4 = 22.6274 (= "abs(-mountCircle / ( 2 * sqrt(2) ))")
  dimension "d831" distance P1 P4 = 22.6274 (= "abs(-mountCircle / ( 2 * sqrt(2) ))")
  dimension "d832" diameter C3 = 4.3 (= "m4Clearance")
  dimension "d833" distance P1 P5 = 22.6274 (= "abs(mountCircle / ( 2 * sqrt(2) ))")
  dimension "d834" distance P1 P5 = 22.6274 (= "abs(-mountCircle / ( 2 * sqrt(2) ))")
  dimension "d835" diameter C4 = 4.3 (= "m4Clearance")
extrude "Extrude36" cut sketch "B Four Mount Holes" no distance stored
sketch "B M4 Nut Pocket 1" plane through (-0.3536, -0.3536, 0) normal (0.7071, 0.7071, 0) x axis (0, 0, 1)
  line L1 (24.7059, 26.2274) -> (26.7843, 22.6274)
  line L2 (20.549, 26.2274) -> (24.7059, 26.2274)
  line L3 (18.4705, 22.6274) -> (20.549, 26.2274)
  line L4 (20.549, 19.0274) -> (18.4705, 22.6274)
  line L5 (24.7059, 19.0274) -> (20.549, 19.0274)
  line L6 (26.7843, 22.6274) -> (24.7059, 19.0274)
  circle C1 centre (22.6274, 22.6274) radius 4.1569
  point P3 (26.7843, 22.6274)
  point P4 (24.7059, 26.2274)
  point P5 (20.549, 26.2274)
  point P6 (18.4705, 22.6274)
  point P7 (20.549, 19.0274)
  point P8 (24.7059, 19.0274)
  point P1 (0, 0)
  point P2 (22.6274, 22.6274)
  coincident C1 P3
  coincident C1 P4
  coincident C1 P5
  coincident C1 P6
  coincident C1 P7
  coincident C1 P8
  equal L1 L2
  equal L1 L3
  equal L1 L4
  equal L1 L5
  equal L1 L6
  horizontal L2
  dimension "d838" distance P1 P2 = 22.6274 (= "abs(mountCircle / ( 2 * sqrt(2) ))")
  dimension "d839" distance P1 P2 = 22.6274 (= "abs(mountCircle / ( 2 * sqrt(2) ))")
  dimension "d840" diameter C1 = 8.3138 (= "2 * ( nutAF ) / sqrt(3)")
extrude "Extrude37" cut sketch "B M4 Nut Pocket 1" profile of L1 L2 L3 L4 L5 L6 no distance stored
sketch "B M4 Nut Pocket 2" plane through (-0.3536, -0.3536, 0) normal (0.7071, 0.7071, 0) x axis (0, 0, 1)
  line L1 (-20.549, 26.2274) -> (-18.4705, 22.6274)
  line L2 (-24.7059, 26.2274) -> (-20.549, 26.2274)
  line L3 (-26.7843, 22.6274) -> (-24.7059, 26.2274)
  line L4 (-24.7059, 19.0274) -> (-26.7843, 22.6274)
  line L5 (-20.549, 19.0274) -> (-24.7059, 19.0274)
  line L6 (-18.4705, 22.6274) -> (-20.549, 19.0274)
  circle C1 centre (-22.6274, 22.6274) radius 4.1569
  point P3 (-18.4705, 22.6274)
  point P4 (-20.549, 26.2274)
  point P5 (-24.7059, 26.2274)
  point P6 (-26.7843, 22.6274)
  point P7 (-24.7059, 19.0274)
  point P8 (-20.549, 19.0274)
  point P1 (0, 0)
  point P2 (-22.6274, 22.6274)
  coincident C1 P3
  coincident C1 P4
  coincident C1 P5
  coincident C1 P6
  coincident C1 P7
  coincident C1 P8
  equal L1 L2
  equal L1 L3
  equal L1 L4
  equal L1 L5
  equal L1 L6
  horizontal L2
  dimension "d843" distance P1 P2 = 22.6274 (= "abs(-mountCircle / ( 2 * sqrt(2) ))")
  dimension "d844" distance P1 P2 = 22.6274 (= "abs(mountCircle / ( 2 * sqrt(2) ))")
  dimension "d845" diameter C1 = 8.3138 (= "2 * ( nutAF ) / sqrt(3)")
extrude "Extrude38" cut sketch "B M4 Nut Pocket 2" profile of L1 L2 L3 L4 L5 L6 no distance stored
sketch "B M4 Nut Pocket 3" plane through (-0.3536, -0.3536, 0) normal (0.7071, 0.7071, 0) x axis (0, 0, 1)
  line L1 (-20.549, -19.0274) -> (-18.4705, -22.6274)
  line L2 (-24.7059, -19.0274) -> (-20.549, -19.0274)
  line L3 (-26.7843, -22.6274) -> (-24.7059, -19.0274)
  line L4 (-24.7059, -26.2274) -> (-26.7843, -22.6274)
  line L5 (-20.549, -26.2274) -> (-24.7059, -26.2274)
  line L6 (-18.4705, -22.6274) -> (-20.549, -26.2274)
  circle C1 centre (-22.6274, -22.6274) radius 4.1569
  point P3 (-18.4705, -22.6274)
  point P4 (-20.549, -19.0274)
  point P5 (-24.7059, -19.0274)
  point P6 (-26.7843, -22.6274)
  point P7 (-24.7059, -26.2274)
  point P8 (-20.549, -26.2274)
  point P1 (0, 0)
  point P2 (-22.6274, -22.6274)
  coincident C1 P3
  coincident C1 P4
  coincident C1 P5
  coincident C1 P6
  coincident C1 P7
  coincident C1 P8
  equal L1 L2
  equal L1 L3
  equal L1 L4
  equal L1 L5
  equal L1 L6
  horizontal L2
  dimension "d848" distance P1 P2 = 22.6274 (= "abs(-mountCircle / ( 2 * sqrt(2) ))")
  dimension "d849" distance P1 P2 = 22.6274 (= "abs(-mountCircle / ( 2 * sqrt(2) ))")
  dimension "d850" diameter C1 = 8.3138 (= "2 * ( nutAF ) / sqrt(3)")
extrude "Extrude39" cut sketch "B M4 Nut Pocket 3" profile of L1 L2 L3 L4 L5 L6 no distance stored
sketch "B M4 Nut Pocket 4" plane through (-0.3536, -0.3536, 0) normal (0.7071, 0.7071, 0) x axis (0, 0, 1)
  line L1 (24.7059, -19.0274) -> (26.7843, -22.6274)
  line L2 (20.549, -19.0274) -> (24.7059, -19.0274)
  line L3 (18.4705, -22.6274) -> (20.549, -19.0274)
  line L4 (20.549, -26.2274) -> (18.4705, -22.6274)
  line L5 (24.7059, -26.2274) -> (20.549, -26.2274)
  line L6 (26.7843, -22.6274) -> (24.7059, -26.2274)
  circle C1 centre (22.6274, -22.6274) radius 4.1569
  point P3 (26.7843, -22.6274)
  point P4 (24.7059, -19.0274)
  point P5 (20.549, -19.0274)
  point P6 (18.4705, -22.6274)
  point P7 (20.549, -26.2274)
  point P8 (24.7059, -26.2274)
  point P1 (0, 0)
  point P2 (22.6274, -22.6274)
  coincident C1 P3
  coincident C1 P4
  coincident C1 P5
  coincident C1 P6
  coincident C1 P7
  coincident C1 P8
  equal L1 L2
  equal L1 L3
  equal L1 L4
  equal L1 L5
  equal L1 L6
  horizontal L2
  dimension "d853" distance P1 P2 = 22.6274 (= "abs(mountCircle / ( 2 * sqrt(2) ))")
  dimension "d854" distance P1 P2 = 22.6274 (= "abs(-mountCircle / ( 2 * sqrt(2) ))")
  dimension "d855" diameter C1 = 8.3138 (= "2 * ( nutAF ) / sqrt(3)")
extrude "Extrude40" cut sketch "B M4 Nut Pocket 4" profile of L1 L2 L3 L4 L5 L6 no distance stored
sketch "B Hub Service Slots" plane through (0, 0, 0) normal (0, 0, 1) x axis (1, 0, 0)
  line L1 (-30.4056, -12.0208) -> (-14.8492, 3.5355)
  line L2 (-12.0208, -30.4056) -> (-30.4056, -12.0208)
  line L3 (3.5355, -14.8492) -> (-12.0208, -30.4056)
  line L4 (-14.8492, 3.5355) -> (3.5355, -14.8492)
  point P1 (0, 0)
  point P2 (-14.8492, 3.5355)
  point P3 (-30.4056, -12.0208)
  point P4 (-12.0208, -30.4056)
  point P5 (3.5355, -14.8492)
  dimension "d858" distance P1 P2 = 14.8492 (= "abs(( -8 mm - 13 mm ) / sqrt(2))")
  dimension "d859" distance P1 P2 = 3.5355 (= "abs(( -8 mm + 13 mm ) / sqrt(2))")
  dimension "d860" distance P1 P3 = 30.4056 (= "abs(( -30 mm - 13 mm ) / sqrt(2))")
  dimension "d861" distance P1 P3 = 12.0208 (= "abs(( -30 mm + 13 mm ) / sqrt(2))")
  dimension "d862" distance P1 P4 = 12.0208 (= "abs(( -30 mm + 13 mm ) / sqrt(2))")
  dimension "d863" distance P1 P4 = 30.4056 (= "abs(( -30 mm - 13 mm ) / sqrt(2))")
  dimension "d864" distance P1 P5 = 3.5355 (= "abs(( -8 mm + 13 mm ) / sqrt(2))")
  dimension "d865" distance P1 P5 = 14.8492 (= "abs(( -8 mm - 13 mm ) / sqrt(2))")
extrude "Extrude41" cut sketch "B Hub Service Slots" distance 76 (= "mountOD")
chamfer "Chamfer2" distance 0.3 (= "bedRelief")
chamfer "Chamfer3" distance 0.5 (= "tubeCornerChamfer")
chamfer "Chamfer4" sketch "A Facet 135 Triangle 1" distance 0.3 (= "tubeRimChamfer")
work_plane "WorkPlane25" RotateAngle 0 ExtraOffset 0
work_plane "WorkPlane26" AlongDistance 75 (= "bodyWidth / 2") ExtraOffset 0
sketch "A End Cord Port" plane through (0, 0, 75) normal (0, 0, 1) x axis (1, 0, 0)
  line L1 (125, 0) -> (0, 0)
  circle C1 centre (125, 0) radius 2.25
  point P1 (0, 0)
  point P2 (125, 0)
  horizontal L1
  dimension "d875" distance P1 P2 = 125 (= "abs(( 1 ) * ( ( 1 ) * cordStation ) + ( 0 ) * ( 0 mm ))")
  dimension "d876" diameter C1 = 4.5
extrude "Extrude40" cut sketch "A End Cord Port" profile of C1 no distance stored
chamfer "Chamfer5" distance 0.3 (= "bedRelief")
work_plane "WorkPlane27" RotateAngle 180 ExtraOffset 0
work_plane "WorkPlane28" AlongDistance 75 (= "bodyWidth / 2") ExtraOffset 0
sketch "A End Cord Port (1)" plane through (0, 0, -75) normal (0, 0, -1) x axis (-1, 0, 0)
  line L1 (-125, 0) -> (0, 0)
  circle C1 centre (-125, 0) radius 2.25
  point P1 (0, 0)
  point P2 (-125, 0)
  horizontal L1
  dimension "d884" distance P1 P2 = 125 (= "abs(( -1 ) * ( ( 1 ) * cordStation ) + ( 0 ) * ( 0 mm ))")
  dimension "d885" diameter C1 = 4.5
extrude "Extrude41" cut sketch "A End Cord Port (1)" profile of C1 no distance stored
chamfer "Chamfer6" distance 0.3 (= "bedRelief")
chamfer "Chamfer1" distance 0.3 (= "bedRelief")
chamfer "Chamfer2" distance 0.5 (= "tubeCornerChamfer")
chamfer "Chamfer3" sketch "A Facet 135 Triangle 1" distance 0.3 (= "tubeRimChamfer")
work_plane "WorkPlane21" RotateAngle 0 ExtraOffset 0
work_plane "WorkPlane22" AlongDistance 75 (= "bodyWidth / 2") ExtraOffset 0
sketch "B End Cord Port" plane through (0, 0, 75) normal (0, 0, 1) x axis (1, 0, 0)
  line L1 (-125, 0) -> (0, 0)
  circle C1 centre (-125, 0) radius 2.25
  point P1 (0, 0)
  point P2 (-125, 0)
  horizontal L1
  dimension "d896" distance P1 P2 = 125 (= "abs(( 1 ) * ( ( -1 ) * cordStation ) + ( 0 ) * ( 0 mm ))")
  dimension "d897" diameter C1 = 4.5
extrude "Extrude42" cut sketch "B End Cord Port" profile of C1 no distance stored
chamfer "Chamfer4" distance 0.3 (= "bedRelief")
work_plane "WorkPlane23" RotateAngle 180 ExtraOffset 0
work_plane "WorkPlane24" AlongDistance 75 (= "bodyWidth / 2") ExtraOffset 0
sketch "B End Cord Port (1)" plane through (0, 0, -75) normal (0, 0, -1) x axis (-1, 0, 0)
  line L1 (125, 0) -> (0, 0)
  circle C1 centre (125, 0) radius 2.25
  point P1 (0, 0)
  point P2 (125, 0)
  horizontal L1
  dimension "d905" distance P1 P2 = 125 (= "abs(( -1 ) * ( ( -1 ) * cordStation ) + ( 0 ) * ( 0 mm ))")
  dimension "d906" diameter C1 = 4.5
extrude "Extrude43" cut sketch "B End Cord Port (1)" profile of C1 no distance stored
chamfer "Chamfer5" distance 0.3 (= "bedRelief")
work_plane "WorkPlane1" AlongDistance 22.6 (= "qRearBase") ExtraOffset 0
sketch "D Rear Holder Blank sketch" plane through (15.9806, 15.9806, 0) normal (0.7071, 0.7071, 0) x axis (0, 0, 1)
  circle C1 centre (0, 0) radius 22
  dimension "d912" diameter C1 = 44 (= "coreOD")
extrude "Extrude1" new body sketch "D Rear Holder Blank sketch" along normal blind 10.2 (= "shoulder + rearSeatDepth")
work_plane "WorkPlane2" AlongDistance 22.6 (= "qRearBase") ExtraOffset 0
sketch "D Seal Relief sketch" plane through (15.9806, 15.9806, 0) normal (0.7071, 0.7071, 0) x axis (0, 0, 1)
  circle C1 centre (0, 0) radius 9.75
  dimension "d917" diameter C1 = 19.5 (= "raceRelief")
extrude "Extrude2" cut sketch "D Seal Relief sketch" along normal blind 10.2 (= "shoulder + rearSeatDepth")
work_plane "WorkPlane3" AlongDistance 25.6 (= "qRearBearing") ExtraOffset 0
sketch "D Rear Bearing Seat sketch" plane through (18.1019, 18.1019, 0) normal (0.7071, 0.7071, 0) x axis (0, 0, 1)
  circle C1 centre (0, 0) radius 11.1
  dimension "d922" diameter C1 = 22.2 (= "seatDiameter")
extrude "Extrude3" cut sketch "D Rear Bearing Seat sketch" along normal blind 7.2 (= "rearSeatDepth")
work_plane "WorkPlane4" AlongDistance 22.6 (= "qRearBase") ExtraOffset 0
sketch "D Support Bolt seed" plane through (15.9806, 15.9806, 0) normal (0.7071, 0.7071, 0) x axis (0, 0, 1)
  line L1 (17, 0) -> (0, 0)
  circle C1 centre (17, 0) radius 1.65
  point P1 (0, 0)
  point P2 (17, 0)
  horizontal L1
  dimension "d927" distance P1 P2 = 17 (= "supportCircle / 2")
  dimension "d928" diameter C1 = 3.3 (= "m3Clearance")
extrude "Extrude4" cut sketch "D Support Bolt seed" profile of C1 along normal blind 10.2 (= "shoulder + rearSeatDepth")
circular_pattern "C-Pattern1" TotalAngle 360
chamfer "Chamfer1" distance 0.4 (= "entryChamfer")
chamfer "Chamfer2" distance 0.3 (= "bedRelief")
work_plane "WorkPlane1" AlongDistance -2.5 (= "qFront - capThickness") ExtraOffset 0
sketch "C Front Bearing Cap Ring sketch" plane through (-1.7678, -1.7678, 0) normal (0.7071, 0.7071, 0) x axis (0, 0, 1)
  circle C1 centre (0, 0) radius 22
  circle C2 centre (0, 0) radius 9.75
  dimension "d937" diameter C1 = 44 (= "coreOD")
  dimension "d938" diameter C2 = 19.5 (= "raceRelief")
extrude "Extrude1" new body sketch "C Front Bearing Cap Ring sketch" along normal blind 3 (= "capThickness")
work_plane "WorkPlane2" AlongDistance -2.5 (= "qFront - capThickness") ExtraOffset 0
sketch "C Front Bearing Cap Bolt seed" plane through (-1.7678, -1.7678, 0) normal (0.7071, 0.7071, 0) x axis (0, 0, 1)
  line L1 (17, 0) -> (0, 0)
  circle C1 centre (17, 0) radius 1.65
  point P1 (0, 0)
  point P2 (17, 0)
  horizontal L1
  dimension "d943" distance P1 P2 = 17 (= "supportCircle / 2")
  dimension "d944" diameter C1 = 3.3 (= "m3Clearance")
extrude "Extrude2" cut sketch "C Front Bearing Cap Bolt seed" profile of C1 along normal blind 3 (= "capThickness")
circular_pattern "C-Pattern1" TotalAngle 360
chamfer "Chamfer1" distance 0.3 (= "bedRelief")
work_plane "WorkPlane1" AlongDistance 32.8 (= "qRearEnd") ExtraOffset 0
sketch "E Rear Bearing Cap Ring sketch" plane through (23.1931, 23.1931, 0) normal (0.7071, 0.7071, 0) x axis (0, 0, 1)
  circle C1 centre (0, 0) radius 22
  circle C2 centre (0, 0) radius 9.75
  dimension "d952" diameter C1 = 44 (= "coreOD")
  dimension "d953" diameter C2 = 19.5 (= "raceRelief")
extrude "Extrude1" new body sketch "E Rear Bearing Cap Ring sketch" along normal blind 3 (= "capThickness")
work_plane "WorkPlane2" AlongDistance 32.8 (= "qRearEnd") ExtraOffset 0
sketch "E Rear Bearing Cap Bolt seed" plane through (23.1931, 23.1931, 0) normal (0.7071, 0.7071, 0) x axis (0, 0, 1)
  line L1 (17, 0) -> (0, 0)
  circle C1 centre (17, 0) radius 1.65
  point P1 (0, 0)
  point P2 (17, 0)
  horizontal L1
  dimension "d958" distance P1 P2 = 17 (= "supportCircle / 2")
  dimension "d959" diameter C1 = 3.3 (= "m3Clearance")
